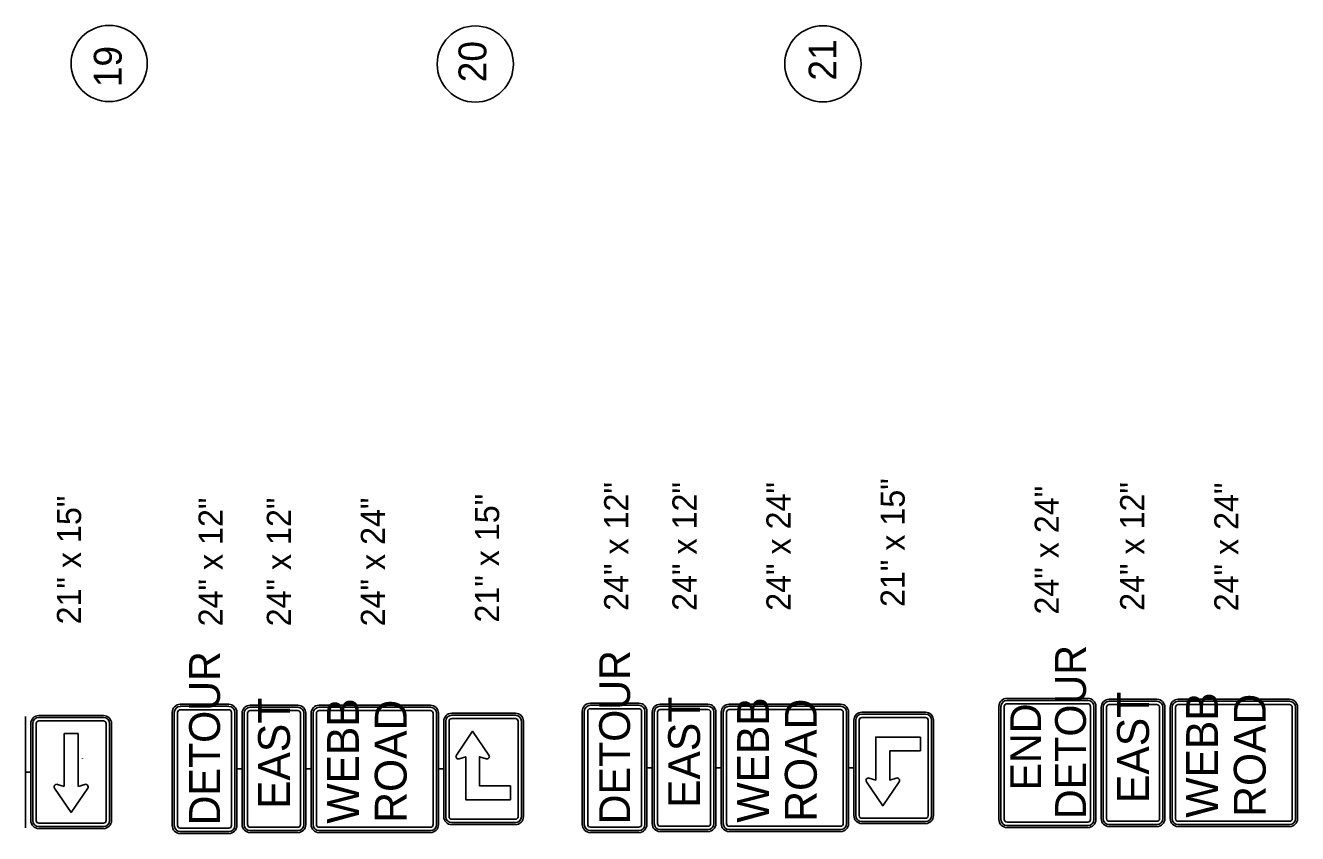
# Model space of a CAD drawing. Extents: x 1149904 to 1171904, y 589308 to 623636.
# Drawn here: x 1156977 to 1163469, y 597728 to 601854 of the extents above; entities that cross this region are included whole.
import ezdxf

# ---------------------------------------------------------------- set-up
doc = ezdxf.new("R2010")
doc.units = 0
doc.layers.add('D_Text_Standard', color=7, linetype='Continuous')
doc.layers.add('SIGNS TRAFFIC', color=7, linetype='Continuous')

msp = doc.modelspace()

# ---------------------------------------------------------------- linework, layer by layer
at = {"layer": 'D_Text_Standard'}
for p, q in [((1158056, 598057.7), (1158083, 598057.7)), ((1158408, 598057.7), (1158435, 598057.7)), ((1159085, 598057.7), (1159112, 598057.7)), ((1160148.9, 598062.9), (1160175.9, 598062.9)), ((1160500.9, 598062.9), (1160527.9, 598062.9)), ((1161177.9, 598062.9), (1161204.9, 598062.9)), ((1156977.1, 598041.8), (1157004.1, 598041.8))]:
    msp.add_line(p, q, dxfattribs=at)
for centre in [(1157404.6, 601659.3), (1159272.8, 601656.7), (1161046.8, 601657.6)]:
    msp.add_circle(centre, 194.5, dxfattribs=at)
at = {"layer": 'SIGNS TRAFFIC'}
for p, q in [((1157014.4, 597794.3), (1157014.4, 598289.3)), ((1157174.2, 597968), (1157174.3, 598237.8)), ((1157174.3, 598237.8), (1157246.4, 598237.8)), ((1157246.5, 598237.8), (1157246.4, 597968)), ((1161545.2, 598149.3), (1161545.2, 598220.4)), ((1157140.5, 597978.9), (1157174.2, 597968)), ((1157246.4, 597968), (1157280.2, 597978.9)), ((1159452.3, 597971.4), (1159452.3, 597900.3))]:
    msp.add_line(p, q, dxfattribs=at)
for points in [[(1157767.3, 598387.7), (1158014.8, 598387.7)], [(1157767.3, 598387.7), (1158014.8, 598387.7)], [(1157767.3, 598377.4), (1158014.8, 598377.4)], [(1158123.7, 598382.7), (1158367.4, 598382.7)], [(1158123.7, 598382.7), (1158367.4, 598382.7)], [(1158123.7, 598372.5), (1158367.4, 598372.5)], [(1158475.7, 598382.7), (1159044.4, 598382.7)], [(1158475.7, 598382.7), (1159044.4, 598382.7)], [(1158475.7, 598372.5), (1159044.4, 598372.5)], [(1159860.1, 598392.9), (1160107.6, 598392.9)], [(1159860.1, 598392.9), (1160107.6, 598392.9)], [(1159860.1, 598382.6), (1160107.6, 598382.6)], [(1160216.5, 598387.9), (1160460.3, 598387.9)], [(1160216.5, 598387.9), (1160460.3, 598387.9)], [(1160216.5, 598377.8), (1160460.3, 598377.8)], [(1160568.5, 598387.9), (1161137.3, 598387.9)], [(1160568.5, 598387.9), (1161137.3, 598387.9)], [(1160568.5, 598377.8), (1161137.3, 598377.8)], [(1161945.1, 597799.4), (1161945.1, 598376.9)], [(1161945.1, 597799.4), (1161945.1, 598376.9)], [(1161955.5, 597799.4), (1161955.5, 598376.9)], [(1161972.6, 598376.9), (1161972.6, 597799.4)], [(1161986.4, 598418.1), (1162398.9, 598418.1)], [(1161986.4, 598418.1), (1162398.9, 598418.1)], [(1161986.4, 598407.8), (1162398.9, 598407.8)], [(1162398.9, 598390.6), (1161986.4, 598390.6)], [(1162412.6, 597799.4), (1162412.6, 598376.9)], [(1162429.8, 598376.9), (1162429.8, 597799.4)], [(1162440.1, 598376.9), (1162440.1, 597799.4)], [(1162440.1, 598376.9), (1162440.1, 597799.4)], [(1162467.1, 597803.8), (1162467.1, 598372.5)], [(1162467.1, 597803.8), (1162467.1, 598372.5)], [(1162477.3, 597803.8), (1162477.3, 598372.5)], [(1162494.2, 598372.5), (1162494.2, 597803.8)], [(1162507.7, 598413.1), (1162751.5, 598413.1)], [(1162507.7, 598413.1), (1162751.5, 598413.1)], [(1162507.7, 598403), (1162751.5, 598403)], [(1162751.5, 598386), (1162507.7, 598386)], [(1162765, 597803.8), (1162765, 598372.5)], [(1162782, 598372.5), (1162782, 597803.8)], [(1162792.1, 598372.5), (1162792.1, 597803.8)], [(1162792.1, 598372.5), (1162792.1, 597803.8)], [(1162819.1, 597803.8), (1162819.1, 598372.5)], [(1162819.1, 597803.8), (1162819.1, 598372.5)], [(1162829.3, 597803.8), (1162829.3, 598372.5)], [(1162846.2, 598372.5), (1162846.2, 597803.8)], [(1162859.8, 598413.1), (1163428.5, 598413.1)], [(1162859.8, 598413.1), (1163428.5, 598413.1)], [(1162859.8, 598403), (1163428.5, 598403)], [(1163428.5, 598386.1), (1162859.8, 598386.1)], [(1163442, 597803.8), (1163442, 598372.5)], [(1163459, 598372.5), (1163459, 597803.8)], [(1163469.1, 598372.5), (1163469.1, 597803.8)], [(1163469.1, 598372.5), (1163469.1, 597803.8)], [(1156977.1, 598326.2), (1156977.1, 597757.5)], [(1156977.1, 598326.2), (1156977.1, 597757.5)], [(1157375.3, 598330.6), (1157045.4, 598330.6)], [(1157045.4, 598320.2), (1157375.3, 598320.2)], [(1157726, 597768.9), (1157726, 598346.4)], [(1157726, 597768.9), (1157726, 598346.4)], [(1157736.4, 597768.9), (1157736.4, 598346.4)], [(1157753.6, 598346.4), (1157753.6, 597768.9)], [(1158014.8, 598360.2), (1157767.3, 598360.2)], [(1158028.5, 597768.9), (1158028.5, 598346.4)], [(1158045.7, 598346.4), (1158045.7, 597768.9)], [(1158056, 598346.4), (1158056, 597768.9)], [(1158056, 598346.4), (1158056, 597768.9)], [(1158083, 597773.3), (1158083, 598342.1)], [(1158083, 597773.3), (1158083, 598342.1)], [(1158093.2, 597773.3), (1158093.2, 598342.1)], [(1158110.1, 598342.1), (1158110.1, 597773.3)], [(1158367.4, 598355.6), (1158123.7, 598355.6)], [(1158380.9, 597773.3), (1158380.9, 598342.1)], [(1158397.9, 598342.1), (1158397.9, 597773.3)], [(1158408, 598342.1), (1158408, 597773.3)], [(1158408, 598342.1), (1158408, 597773.3)], [(1158435, 597773.3), (1158435, 598342.1)], [(1158435, 597773.3), (1158435, 598342.1)], [(1158445.2, 597773.3), (1158445.2, 598342.1)], [(1158462.1, 598342.1), (1158462.1, 597773.3)], [(1159044.4, 598355.6), (1158475.7, 598355.6)], [(1159057.9, 597773.3), (1159057.9, 598342.1)], [(1159074.9, 598342.1), (1159074.9, 597773.3)], [(1159085, 598342.1), (1159085, 597773.3)], [(1159085, 598342.1), (1159085, 597773.3)], [(1159477.7, 598342.1), (1159152.7, 598342.1)], [(1159152.7, 598342.1), (1159477.7, 598342.1)], [(1159152.7, 598331.9), (1159477.7, 598331.9)], [(1159477.7, 598315), (1159152.7, 598315)], [(1159818.9, 597774.2), (1159818.9, 598351.7)], [(1159818.9, 597774.2), (1159818.9, 598351.7)], [(1159829.2, 597774.2), (1159829.2, 598351.7)], [(1159846.4, 598351.7), (1159846.4, 597774.2)], [(1160107.6, 598365.4), (1159860.1, 598365.4)], [(1160121.4, 597774.2), (1160121.4, 598351.7)], [(1160138.6, 598351.7), (1160138.6, 597774.2)], [(1160148.9, 598351.7), (1160148.9, 597774.2)], [(1160148.9, 598351.7), (1160148.9, 597774.2)], [(1160175.9, 597778.6), (1160175.9, 598347.3)], [(1160175.9, 597778.6), (1160175.9, 598347.3)], [(1160186.1, 597778.6), (1160186.1, 598347.3)], [(1160203, 598347.3), (1160203, 597778.6)], [(1160460.3, 598360.8), (1160216.5, 598360.8)], [(1160473.8, 597778.6), (1160473.8, 598347.3)], [(1160490.7, 598347.3), (1160490.7, 597778.6)], [(1160500.9, 598347.3), (1160500.9, 597778.6)], [(1160500.9, 598347.3), (1160500.9, 597778.6)], [(1160527.9, 597778.6), (1160527.9, 598347.3)], [(1160527.9, 597778.6), (1160527.9, 598347.3)], [(1160538, 597778.6), (1160538, 598347.3)], [(1160555, 598347.3), (1160555, 597778.6)], [(1161137.3, 598360.8), (1160568.5, 598360.8)], [(1161150.8, 597778.6), (1161150.8, 598347.3)], [(1161167.7, 598347.3), (1161167.7, 597778.6)], [(1161177.9, 598347.3), (1161177.9, 597778.6)], [(1161177.9, 598347.3), (1161177.9, 597778.6)], [(1161204.9, 597819.2), (1161204.9, 598306.7)], [(1161204.9, 598306.7), (1161204.9, 597819.2)], [(1161215.1, 598306.7), (1161215.1, 597819.2)], [(1161232, 597819.2), (1161232, 598306.7)], [(1161245.5, 598347.3), (1161570.5, 598347.3)], [(1161570.5, 598347.3), (1161245.5, 598347.3)], [(1161570.5, 598337.1), (1161245.5, 598337.1)], [(1161245.5, 598320.2), (1161570.5, 598320.2)], [(1161584, 598306.7), (1161584, 597819.2)], [(1161601, 597819.2), (1161601, 598306.7)], [(1161611.1, 598306.7), (1161611.1, 597819.2)], [(1161611.1, 597819.2), (1161611.1, 598306.7)], [(1157004.1, 598289.3), (1157004.1, 597794.3)], [(1157031.6, 598289.3), (1157031.6, 597794.3)], [(1157375.3, 598303.1), (1157045.4, 598303.1)], [(1157389.1, 597794.3), (1157389.1, 598289.3)], [(1157406.3, 598289.3), (1157406.3, 597794.3)], [(1157416.6, 597794.3), (1157416.6, 598289.3)], [(1159112, 598301.4), (1159112, 597813.9)], [(1159112, 597813.9), (1159112, 598301.4)], [(1159122.2, 597813.9), (1159122.2, 598301.4)], [(1159139.1, 598301.4), (1159139.1, 597813.9)], [(1159176.2, 598128.7), (1159259.3, 598250.5), (1159342.5, 598128.7)], [(1159491.2, 597813.9), (1159491.2, 598301.4)], [(1159508.1, 598301.4), (1159508.1, 597813.9)], [(1159518.3, 597813.9), (1159518.3, 598301.4)], [(1159518.3, 598301.4), (1159518.3, 597813.9)], [(1161545.2, 598220.4), (1161316.6, 598220.4), (1161316.7, 598000.5), (1161283.4, 598011.2)], [(1157268.2, 598111.9), (1157268.1, 598111.8)], [(1159452.3, 597900.3), (1159223.8, 597900.3), (1159223.8, 598120.1), (1159190.6, 598109.4)], [(1159328.1, 598109.4), (1159294.9, 598120.1), (1159294.9, 597971.4), (1159452.3, 597971.4)], [(1161421, 598011.2), (1161387.8, 598000.5), (1161387.7, 598149.3), (1161545.2, 598149.3)], [(1161269, 597991.9), (1161352.2, 597870.1), (1161435.4, 597991.9)], [(1157294.8, 597959.3), (1157210.3, 597835.6), (1157125.9, 597959.3)], [(1159152.7, 597800.4), (1159477.7, 597800.4)], [(1161570.5, 597805.7), (1161245.5, 597805.7)], [(1161245.5, 597788.7), (1161570.5, 597788.7)], [(1162507.7, 597790.2), (1162751.5, 597790.2)], [(1162859.8, 597790.2), (1163428.5, 597790.2)], [(1157045.4, 597780.6), (1157375.3, 597780.6)], [(1157375.3, 597763.4), (1157045.4, 597763.4)], [(1157045.4, 597753.1), (1157375.3, 597753.1)], [(1157767.3, 597755.2), (1158014.8, 597755.2)], [(1158014.8, 597738), (1157767.3, 597738)], [(1158014.8, 597727.7), (1157767.3, 597727.7)], [(1158014.8, 597727.7), (1157767.3, 597727.7)], [(1158123.7, 597759.8), (1158367.4, 597759.8)], [(1158367.4, 597742.9), (1158123.7, 597742.9)], [(1158367.4, 597732.7), (1158123.7, 597732.7)], [(1158367.4, 597732.7), (1158123.7, 597732.7)], [(1158475.7, 597759.8), (1159044.4, 597759.8)], [(1159044.4, 597742.8), (1158475.7, 597742.8)], [(1159044.4, 597732.7), (1158475.7, 597732.7)], [(1159044.4, 597732.7), (1158475.7, 597732.7)], [(1159477.7, 597783.5), (1159152.7, 597783.5)], [(1159152.7, 597773.3), (1159477.7, 597773.3)], [(1159477.7, 597773.3), (1159152.7, 597773.3)], [(1159860.1, 597760.5), (1160107.6, 597760.5)], [(1160107.6, 597743.3), (1159860.1, 597743.3)], [(1160107.6, 597732.9), (1159860.1, 597732.9)], [(1160107.6, 597732.9), (1159860.1, 597732.9)], [(1160216.5, 597765), (1160460.3, 597765)], [(1160460.3, 597748.1), (1160216.5, 597748.1)], [(1160460.3, 597737.9), (1160216.5, 597737.9)], [(1160460.3, 597737.9), (1160216.5, 597737.9)], [(1160568.5, 597765), (1161137.3, 597765)], [(1161137.3, 597748.1), (1160568.5, 597748.1)], [(1161137.3, 597737.9), (1160568.5, 597737.9)], [(1161137.3, 597737.9), (1160568.5, 597737.9)], [(1161570.5, 597778.6), (1161245.5, 597778.6)], [(1161245.5, 597778.6), (1161570.5, 597778.6)], [(1161986.4, 597785.7), (1162398.9, 597785.7)], [(1162398.9, 597768.5), (1161986.4, 597768.5)], [(1162398.9, 597758.1), (1161986.4, 597758.1)], [(1162398.9, 597758.1), (1161986.4, 597758.1)], [(1162751.5, 597773.3), (1162507.7, 597773.3)], [(1162751.5, 597763.1), (1162507.7, 597763.1)], [(1162751.5, 597763.1), (1162507.7, 597763.1)], [(1163428.5, 597773.3), (1162859.8, 597773.3)], [(1163428.5, 597763.1), (1162859.8, 597763.1)], [(1163428.5, 597763.1), (1162859.8, 597763.1)]]:
    msp.add_lwpolyline(points, dxfattribs=at)
for centre, radius, start, end in [((1157767.3, 598346.4), 41.2, 90, 180), ((1157767.3, 598346.4), 41.2, 90, 180), ((1157767.3, 598346.4), 30.9, 90, 180), ((1158014.8, 598346.4), 41.2, 360, 90), ((1158014.8, 598346.4), 41.2, 360, 90), ((1158014.8, 598346.4), 30.9, 360, 90), ((1158123.7, 598342.1), 40.6, 90, 180), ((1158123.7, 598342.1), 40.6, 90, 180), ((1158123.7, 598342.1), 30.5, 90, 180), ((1158367.4, 598342.1), 40.6, 360, 90), ((1158367.4, 598342.1), 40.6, 360, 90), ((1158367.4, 598342.1), 30.5, 360, 90), ((1158475.7, 598342.1), 40.6, 90, 180), ((1158475.7, 598342.1), 40.6, 90, 180), ((1158475.7, 598342.1), 30.5, 90, 180), ((1159044.4, 598342.1), 40.6, 360, 90), ((1159044.4, 598342.1), 40.6, 360, 90), ((1159044.4, 598342.1), 30.5, 360, 90), ((1159860.1, 598351.7), 41.2, 90, 180), ((1159860.1, 598351.7), 41.2, 90, 180), ((1159860.1, 598351.7), 30.9, 90, 180), ((1160107.6, 598351.7), 41.2, 360, 90), ((1160107.6, 598351.7), 41.2, 360, 90), ((1160107.6, 598351.7), 30.9, 360, 90), ((1160216.5, 598347.3), 40.6, 90, 180), ((1160216.5, 598347.3), 40.6, 90, 180), ((1160216.5, 598347.3), 30.5, 90, 180), ((1160460.3, 598347.3), 40.6, 360, 90), ((1160460.3, 598347.3), 40.6, 360, 90), ((1160460.3, 598347.3), 30.5, 360, 90), ((1160568.5, 598347.3), 40.6, 90, 180), ((1160568.5, 598347.3), 40.6, 90, 180), ((1160568.5, 598347.3), 30.5, 90, 180), ((1161137.3, 598347.3), 40.6, 360, 90), ((1161137.3, 598347.3), 40.6, 360, 90), ((1161137.3, 598347.3), 30.5, 360, 90), ((1161986.4, 598376.9), 41.2, 90, 180), ((1161986.4, 598376.9), 41.2, 90, 180), ((1161986.4, 598376.9), 30.9, 90, 180), ((1161986.4, 598376.9), 13.7, 90, 180), ((1162398.9, 598376.9), 41.2, 360, 90), ((1162398.9, 598376.9), 41.2, 360, 90), ((1162398.9, 598376.9), 30.9, 360, 90), ((1162398.9, 598376.9), 13.7, 360, 90), ((1162507.7, 598372.5), 40.6, 90, 180), ((1162507.7, 598372.5), 40.6, 90, 180), ((1162507.7, 598372.5), 30.5, 90, 180), ((1162507.7, 598372.5), 13.5, 90, 180), ((1162751.5, 598372.5), 40.6, 360, 90), ((1162751.5, 598372.5), 40.6, 360, 90), ((1162751.5, 598372.5), 30.5, 360, 90), ((1162751.5, 598372.5), 13.5, 360, 90), ((1162859.8, 598372.5), 40.6, 90, 180), ((1162859.8, 598372.5), 40.6, 90, 180), ((1162859.8, 598372.5), 30.5, 90, 180), ((1162859.8, 598372.5), 13.5, 90, 180), ((1163428.5, 598372.5), 40.6, 360, 90), ((1163428.5, 598372.5), 40.6, 360, 90), ((1163428.5, 598372.5), 30.5, 360, 90), ((1163428.5, 598372.5), 13.5, 360, 90), ((1157045.4, 598289.3), 41.2, 90, 180), ((1157045.4, 598289.3), 30.9, 90, 180), ((1157375.3, 598289.3), 41.2, 360, 90), ((1157375.3, 598289.3), 30.9, 360, 90), ((1157767.3, 598346.4), 13.7, 90, 180), ((1158014.8, 598346.4), 13.7, 360, 90), ((1158123.7, 598342.1), 13.5, 90, 180), ((1158367.4, 598342.1), 13.5, 360, 90), ((1158475.7, 598342.1), 13.5, 90, 180), ((1159044.4, 598342.1), 13.5, 360, 90), ((1159152.7, 598301.4), 40.6, 90, 180), ((1159152.7, 598301.4), 40.6, 90, 180), ((1159152.7, 598301.4), 30.5, 90, 180), ((1159152.7, 598301.4), 13.5, 90, 180), ((1159477.7, 598301.4), 40.6, 360, 90), ((1159477.7, 598301.4), 40.6, 360, 90), ((1159477.7, 598301.4), 30.5, 360, 90), ((1159477.7, 598301.4), 13.5, 360, 90), ((1159860.1, 598351.7), 13.7, 90, 180), ((1160107.6, 598351.7), 13.7, 360, 90), ((1160216.5, 598347.3), 13.5, 90, 180), ((1160460.3, 598347.3), 13.5, 360, 90), ((1160568.5, 598347.3), 13.5, 90, 180), ((1161137.3, 598347.3), 13.5, 360, 90), ((1161245.5, 598306.7), 40.6, 90, 180), ((1161245.5, 598306.7), 40.6, 90, 180), ((1161245.5, 598306.7), 30.5, 90, 180), ((1161245.5, 598306.7), 13.5, 90, 180), ((1161570.5, 598306.7), 40.6, 360, 90), ((1161570.5, 598306.7), 40.6, 360, 90), ((1161570.5, 598306.7), 30.5, 360, 90), ((1161570.5, 598306.7), 13.5, 360, 90), ((1157045.4, 598289.3), 13.7, 90, 180), ((1157375.3, 598289.3), 13.7, 360, 90), ((1159186.7, 598121.5), 12.7, 145.67628, 287.81284), ((1159332, 598121.5), 12.7, 252.18719, 34.32372), ((1161279.5, 597999.1), 12.7, 72.18716, 214.32372), ((1161424.9, 597999.1), 12.7, 325.67628, 107.81281), ((1157136.6, 597966.6), 12.9, 72.18719, 214.32372), ((1157284.1, 597966.6), 12.9, 325.67628, 107.81284), ((1157045.4, 597794.3), 41.2, 180, 270), ((1157045.4, 597794.3), 30.9, 180, 270), ((1157045.4, 597794.3), 13.7, 180, 270), ((1157375.3, 597794.3), 41.2, 270, 0), ((1157375.3, 597794.3), 30.9, 270, 0), ((1157375.3, 597794.3), 13.7, 270, 0), ((1159152.7, 597813.9), 40.6, 180, 270), ((1159152.7, 597813.9), 40.6, 180, 270), ((1159152.7, 597813.9), 30.5, 180, 270), ((1159152.7, 597813.9), 13.5, 180, 270), ((1159477.7, 597813.9), 40.6, 270, 0), ((1159477.7, 597813.9), 40.6, 270, 0), ((1159477.7, 597813.9), 30.5, 270, 0), ((1159477.7, 597813.9), 13.5, 270, 0), ((1161245.5, 597819.2), 40.6, 180, 270), ((1161245.5, 597819.2), 40.6, 180, 270), ((1161245.5, 597819.2), 30.5, 180, 270), ((1161245.5, 597819.2), 13.5, 180, 270), ((1161570.5, 597819.2), 40.6, 270, 0), ((1161570.5, 597819.2), 40.6, 270, 0), ((1161570.5, 597819.2), 30.5, 270, 0), ((1161570.5, 597819.2), 13.5, 270, 0), ((1161986.4, 597799.4), 41.2, 180, 270), ((1161986.4, 597799.4), 41.2, 180, 270), ((1161986.4, 597799.4), 30.9, 180, 270), ((1161986.4, 597799.4), 13.7, 180, 270), ((1162398.9, 597799.4), 41.2, 270, 360), ((1162398.9, 597799.4), 41.2, 270, 360), ((1162398.9, 597799.4), 30.9, 270, 360), ((1162398.9, 597799.4), 13.7, 270, 360), ((1162507.7, 597803.8), 40.6, 180, 270), ((1162507.7, 597803.8), 40.6, 180, 270), ((1162507.7, 597803.8), 30.5, 180, 270), ((1162507.7, 597803.8), 13.5, 180, 270), ((1162751.5, 597803.8), 40.6, 270, 360), ((1162751.5, 597803.8), 40.6, 270, 360), ((1162751.5, 597803.8), 30.5, 270, 360), ((1162751.5, 597803.8), 13.5, 270, 360), ((1162859.8, 597803.8), 40.6, 180, 270), ((1162859.8, 597803.8), 40.6, 180, 270), ((1162859.8, 597803.8), 30.5, 180, 270), ((1162859.8, 597803.8), 13.5, 180, 270), ((1163428.5, 597803.8), 40.6, 270, 360), ((1163428.5, 597803.8), 40.6, 270, 360), ((1163428.5, 597803.8), 30.5, 270, 360), ((1163428.5, 597803.8), 13.5, 270, 360), ((1157767.3, 597768.9), 41.2, 180, 270), ((1157767.3, 597768.9), 41.2, 180, 270), ((1157767.3, 597768.9), 30.9, 180, 270), ((1157767.3, 597768.9), 13.7, 180, 270), ((1158014.8, 597768.9), 41.2, 270, 360), ((1158014.8, 597768.9), 41.2, 270, 360), ((1158014.8, 597768.9), 30.9, 270, 360), ((1158014.8, 597768.9), 13.7, 270, 360), ((1158123.7, 597773.3), 40.6, 180, 270), ((1158123.7, 597773.3), 40.6, 180, 270), ((1158123.7, 597773.3), 30.5, 180, 270), ((1158123.7, 597773.3), 13.5, 180, 270), ((1158367.4, 597773.3), 40.6, 270, 360), ((1158367.4, 597773.3), 40.6, 270, 360), ((1158367.4, 597773.3), 30.5, 270, 360), ((1158367.4, 597773.3), 13.5, 270, 360), ((1158475.7, 597773.3), 40.6, 180, 270), ((1158475.7, 597773.3), 40.6, 180, 270), ((1158475.7, 597773.3), 30.5, 180, 270), ((1158475.7, 597773.3), 13.5, 180, 270), ((1159044.4, 597773.3), 40.6, 270, 360), ((1159044.4, 597773.3), 40.6, 270, 360), ((1159044.4, 597773.3), 30.5, 270, 360), ((1159044.4, 597773.3), 13.5, 270, 360), ((1159860.1, 597774.2), 41.2, 180, 270), ((1159860.1, 597774.2), 41.2, 180, 270), ((1159860.1, 597774.2), 30.9, 180, 270), ((1159860.1, 597774.2), 13.7, 180, 270), ((1160107.6, 597774.2), 41.2, 270, 360), ((1160107.6, 597774.2), 41.2, 270, 360), ((1160107.6, 597774.2), 30.9, 270, 360), ((1160107.6, 597774.2), 13.7, 270, 360), ((1160216.5, 597778.6), 40.6, 180, 270), ((1160216.5, 597778.6), 40.6, 180, 270), ((1160216.5, 597778.6), 30.5, 180, 270), ((1160216.5, 597778.6), 13.5, 180, 270), ((1160460.3, 597778.6), 40.6, 270, 360), ((1160460.3, 597778.6), 40.6, 270, 360), ((1160460.3, 597778.6), 30.5, 270, 360), ((1160460.3, 597778.6), 13.5, 270, 360), ((1160568.5, 597778.6), 40.6, 180, 270), ((1160568.5, 597778.6), 40.6, 180, 270), ((1160568.5, 597778.6), 30.5, 180, 270), ((1160568.5, 597778.6), 13.5, 180, 270), ((1161137.3, 597778.6), 40.6, 270, 360), ((1161137.3, 597778.6), 40.6, 270, 360), ((1161137.3, 597778.6), 30.5, 270, 360), ((1161137.3, 597778.6), 13.5, 270, 360)]:
    msp.add_arc(centre, radius, start, end, dxfattribs=at)

# ---------------------------------------------------------------- texts
at = {"layer": 'D_Text_Standard'}
for s, height, p in [('20', 142, (1159329.2, 601563.2)), ('21', 142, (1161116.1, 601571.8)), ('19', 142, (1157468.1, 601537.9)), ('24" x 12"', 123.19, (1160053.5, 598864.9)), ('24" x 12"', 123.19, (1160402, 598864.9)), ('24" x 24"', 123.19, (1160881.7, 598864.9)), ('21" x 15"', 123.19, (1161464.3, 598884.3)), ('24" x 24"', 123.19, (1162250.8, 598845.8)), ('24" x 12"', 123.19, (1162686.8, 598864.9)), ('24" x 24"', 123.19, (1163167.5, 598862.5)), ('21" x 15"', 123.19, (1157261.1, 598795.5)), ('24" x 12"', 123.19, (1157983.6, 598785.6)), ('24" x 12"', 123.19, (1158332.1, 598785.6)), ('24" x 24"', 123.19, (1158811.9, 598785.6)), ('21" x 15"', 123.19, (1159394.5, 598805))]:
    msp.add_text(s, height=height, rotation=90, dxfattribs=at).set_placement(p)
at = {"layer": 'SIGNS TRAFFIC'}
for s, height, p in [('DETOUR', 157.5, (1157969.8, 597769.6)), ('DETOUR', 157.5, (1160062.7, 597774.9)), ('DETOUR', 157.5, (1162389.2, 597801.5)), ('EAST', 162.5, (1162710.9, 597883.8)), ('WEBB', 162.5, (1163062.9, 597808.8)), ('EAST', 162.5, (1158326.8, 597853.4)), ('WEBB', 162.5, (1158678.8, 597778.4)), ('ROAD', 162.5, (1158922.5, 597783.2)), ('EAST', 162.5, (1160419.7, 597858.6)), ('WEBB', 162.5, (1160771.6, 597783.6)), ('ROAD', 162.5, (1161015.4, 597788.5)), ('END', 157.5, (1162160.3, 597947.4)), ('ROAD', 162.5, (1163306.6, 597813.7))]:
    msp.add_text(s, height=height, rotation=90, dxfattribs=at).set_placement(p)

doc.saveas('drawing.dxf')
